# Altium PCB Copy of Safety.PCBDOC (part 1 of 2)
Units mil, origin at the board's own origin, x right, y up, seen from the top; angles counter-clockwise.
Board outline 11000 x 3900 mil, 4 copper layers (Top Layer, Grounds, +5V, Bottom Layer); 225 components, 170 nets, 779 pads, 129 vias.
Unrouted connection lines stored in the file: 11.
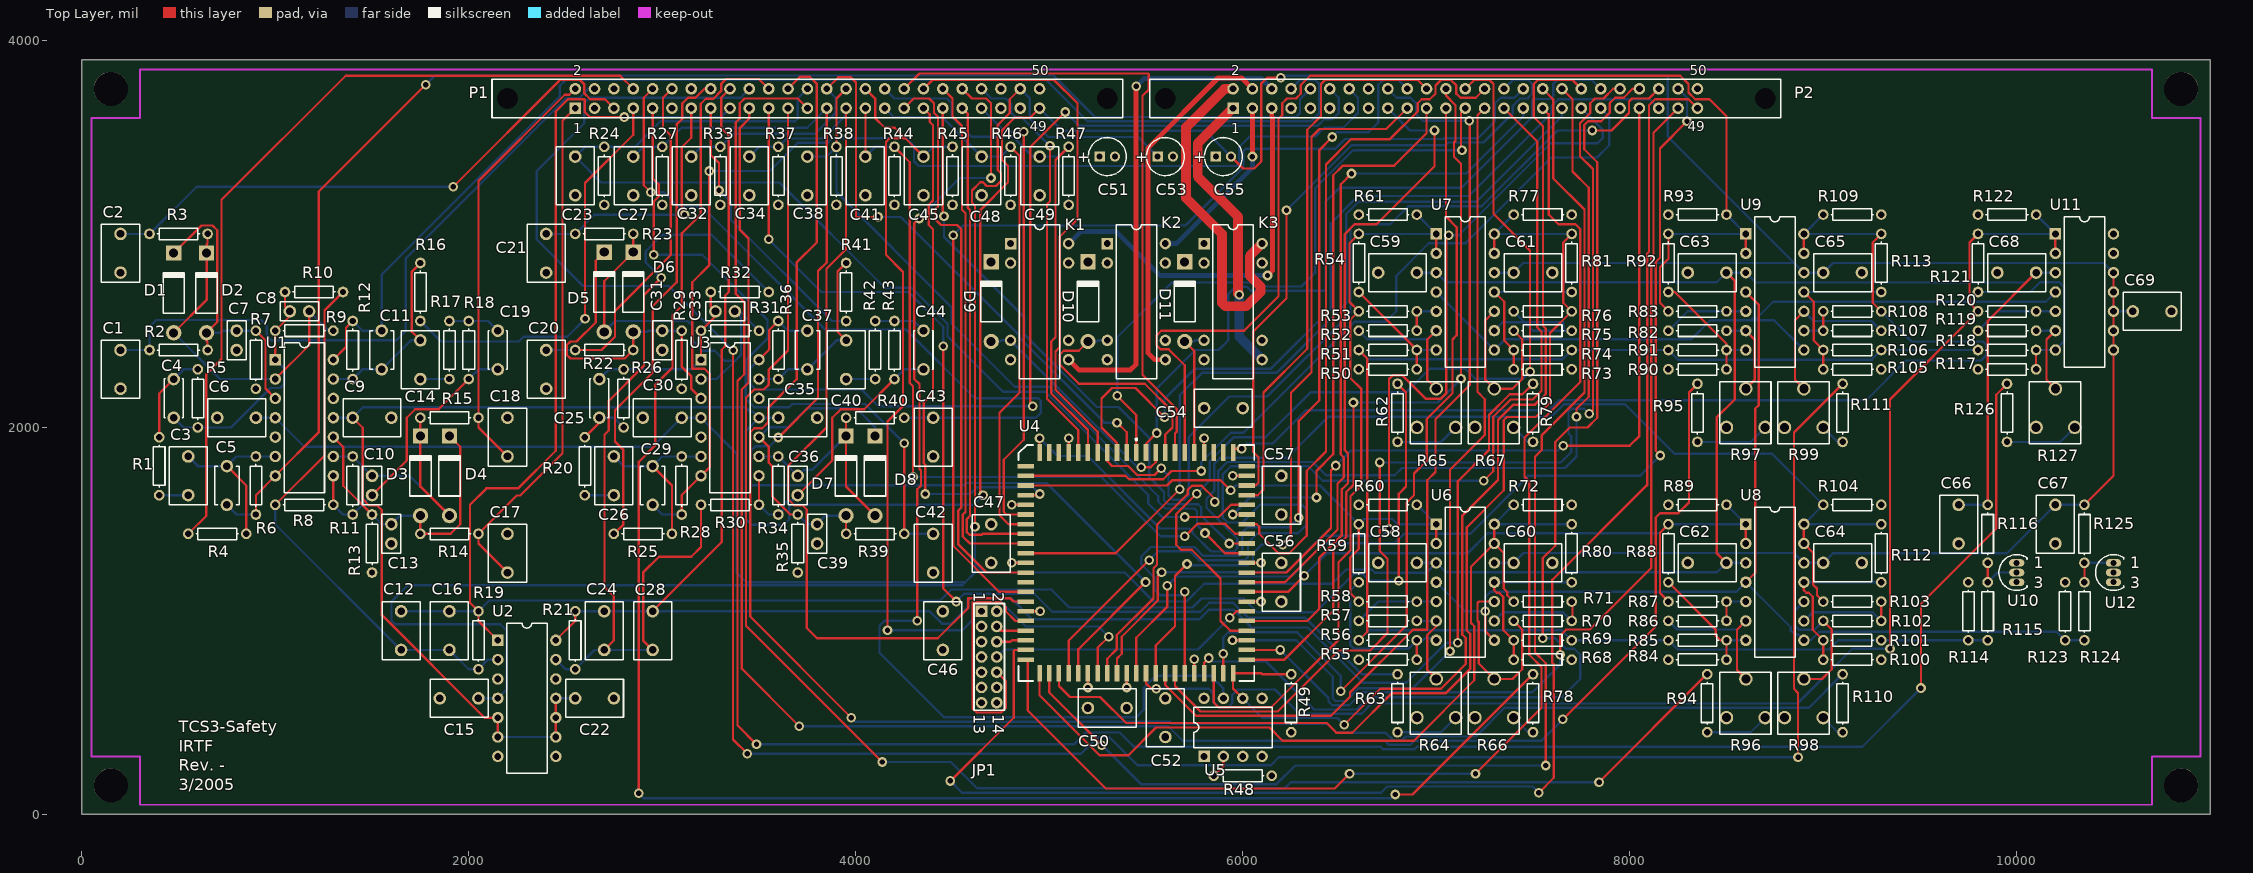
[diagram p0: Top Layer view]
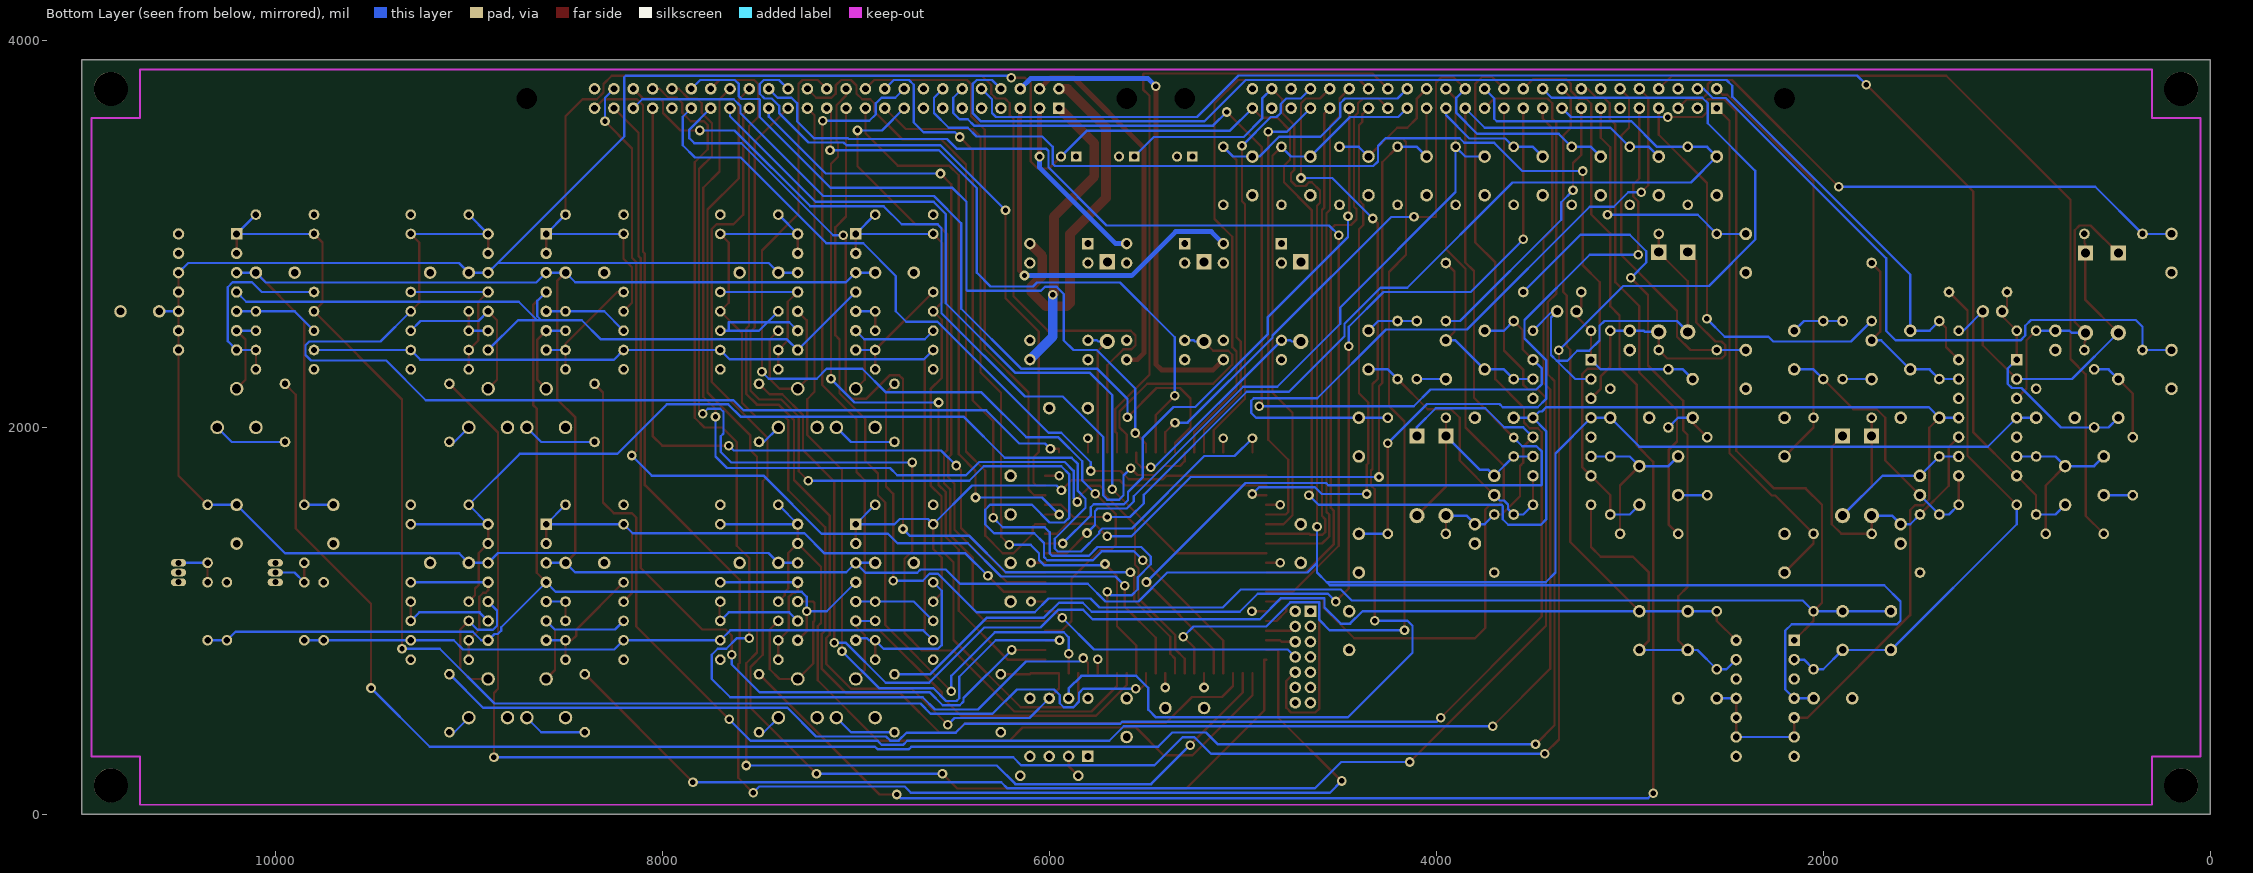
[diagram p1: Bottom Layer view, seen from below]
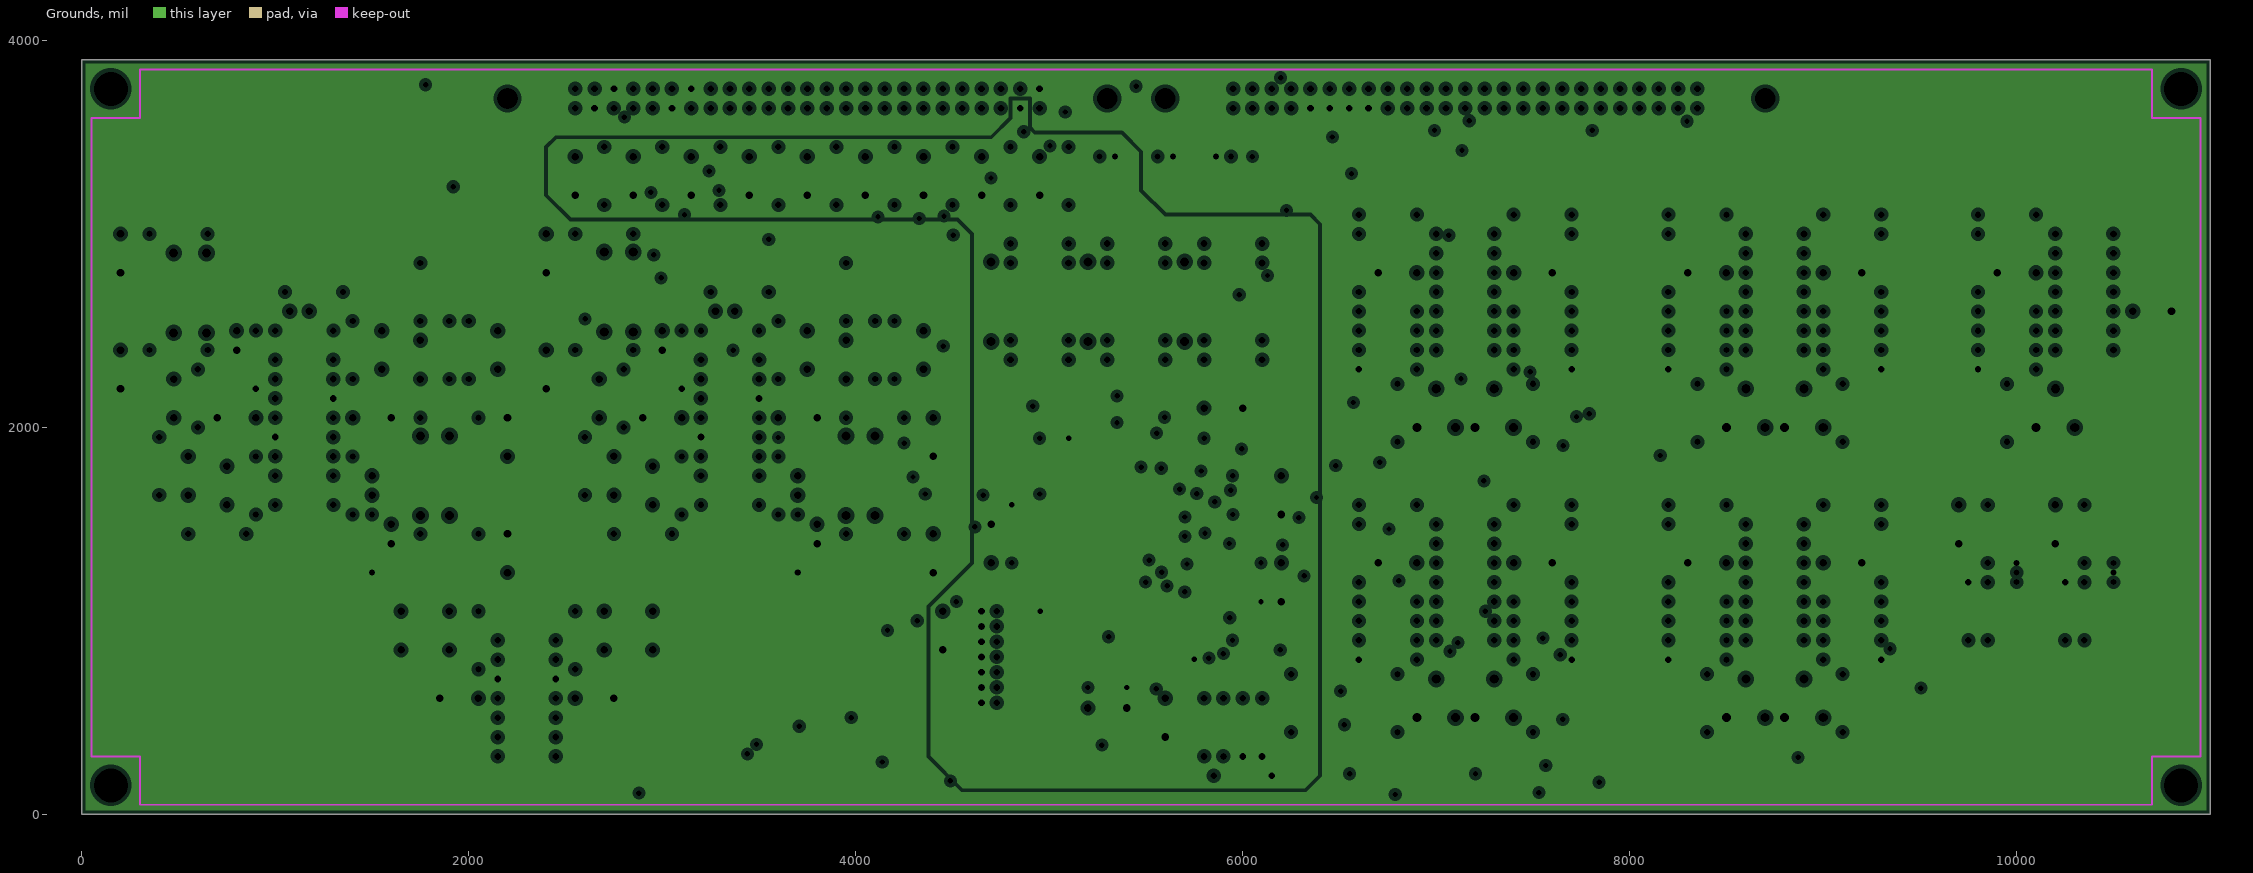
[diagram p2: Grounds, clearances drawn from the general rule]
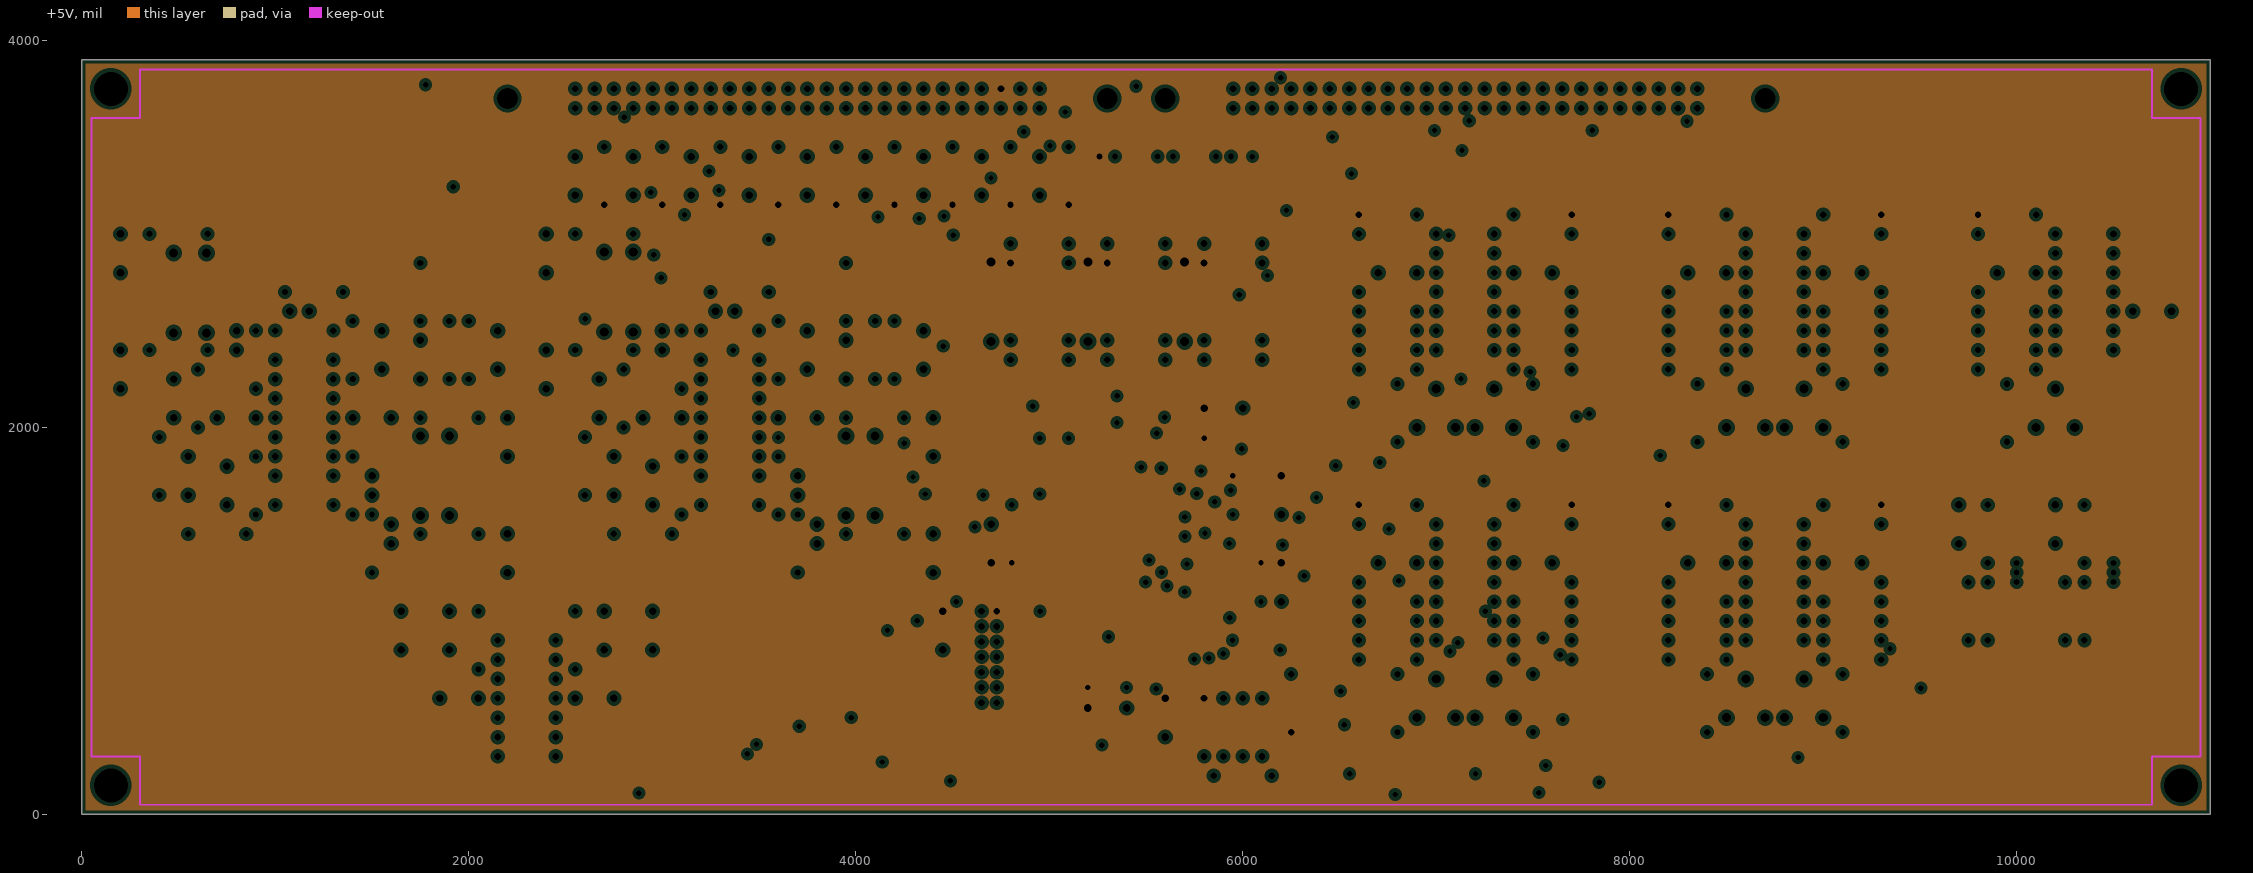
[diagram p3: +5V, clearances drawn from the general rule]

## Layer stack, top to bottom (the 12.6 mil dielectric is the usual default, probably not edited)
Top Layer: signal copper 1.4
Dielectric: core 12.6, FR-4, Dk 4.8
Grounds: plane copper 1.4, net (Multiple Nets)
Dielectric: prepreg 12.6, FR-4, Dk 4.8
+5V: plane copper 1.4, net VCC
Dielectric: core 12.6, FR-4, Dk 4.8
Bottom Layer: signal copper 1.4

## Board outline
0,0 11000,0 11000,3900 0,3900

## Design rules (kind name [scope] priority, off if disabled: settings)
Clearance [All] p1: gap=10
ComponentClearance [All] p1: gap=10 collisioncheckmode=0
HoleSize [All] p1: absolutevalues=TRUE maxlimit=200 minlimit=1 maxpercent=80.000 minpercent=20.000
PlaneClearance "Voltage Reg" [(InNet('NetR124_1') OR InNet('NetR115_1'))] p1: clearance=10
PlaneClearance [All] p2: clearance=20
PlaneConnect [All] p1: planeconnectstyle=Relief reliefexpansion=20 reliefentries=4 reliefconductorwidth=12 reliefairgap=12
PolygonConnect [All] p1: connectstyle=Relief reliefconductorwidth=10 reliefentries=4 polygonreliefangle="90 Angle"
RoomDefinition "U_Fault Comp" [InComponentClass('U_Fault Comp')] p1: confinementstyle=ConfineIn formatcopy=TRUE lockcomponents=FALSE outline 6553.27,753.27 6553.27,3146.73 10146.73,3146.73 10146.73,3101.73 10547.72,3101.73 10547.72,2712.36 10863.54,2712.36 10863.54,2487.64 10642.82,2487.64 10642.82,1143.66 10396.5,1143.66 10396.5,853.5 9346.73,853.5 9346.73,753.27 9146.73,753.27 9146.73,378.27 6753.27,378.27 6753.27,753.27
RoomDefinition "U_Fault Comp_1" [InComponentClass('U_Fault Comp')] p2: confinementstyle=ConfineIn formatcopy=TRUE lockcomponents=FALSE outline 6553.27,753.27 6553.27,3146.73 10146.73,3146.73 10146.73,3101.73 10547.72,3101.73 10547.72,2712.36 10863.54,2712.36 10863.54,2487.64 10642.82,2487.64 10642.82,1143.66 10396.5,1143.66 10396.5,853.5 9346.73,853.5 9346.73,753.27 9146.73,753.27 9146.73,378.27 6753.27,378.27 6753.27,753.27
RoomDefinition "U_Dec Tach" [InComponentClass('U_Dec Tach')] p3: confinementstyle=ConfineIn formatcopy=TRUE lockcomponents=FALSE outline 1786.46,487.64 1786.46,712.36 2287.64,712.36 2287.64,3063.54 2512.36,3063.54 2512.36,3046.73 2896.73,3046.73 2896.73,2959.53 2919.06,2959.53 2919.06,2896.73 3996.73,2896.73 3996.73,2596.73 4246.73,2596.73 4246.73,2549.69 4413.15,2549.69 4413.15,2113.54 4512.36,2113.54 4512.36,1186.46 3062.36,1186.46 3062.36,786.46 2813.54,786.46 2813.54,487.64
RoomDefinition "Safety Top" [InComponentClass('Safety Top')] p4: confinementstyle=ConfineIn formatcopy=TRUE lockcomponents=FALSE outline 2106.06,3502 2106.06,3887.98 8793.94,3887.98 8793.94,3502 6012.36,3502 6012.36,3287.64 5127.6,3287.64 5127.6,3502
RoomDefinition "U_Fault Logic" [InComponentClass('U_Fault Logic')] p5: confinementstyle=ConfineIn formatcopy=TRUE lockcomponents=FALSE outline 2237.64,3136.46 2237.64,3463.54 2478.27,3463.54 2478.27,3496.73 5371.73,3496.73 5371.73,3061.57 6147.72,3061.57 6147.72,1813.54 6312.36,1813.54 6312.36,1036.46 6296.73,1036.46 6296.73,378.27 6196.73,378.27 6196.73,153.27 5803.27,153.27 5803.27,252.28 5733.31,252.28 5733.31,277.02 4586.06,277.02 4586.06,786.46 4337.64,786.46 4337.64,3103.27 2478.27,3103.27 2478.27,3136.46
RoomDefinition "U_HA Tach" [InComponentClass('U_HA Tach')] p6: confinementstyle=ConfineIn formatcopy=TRUE lockcomponents=FALSE outline 87.64,2136.46 87.64,3063.54 312.36,3063.54 312.36,3046.73 696.73,3046.73 696.73,2954.53 714.06,2954.53 714.06,2896.73 1796.73,2896.73 1796.73,2596.73 2046.73,2596.73 2046.73,2549.69 2213.15,2549.69 2213.15,2113.54 2312.36,2113.54 2312.36,1001.73 2497.72,1001.73 2497.72,198.27 2102.28,198.27 2102.28,703.27 2003.27,703.27 2003.27,786.46 1537.64,786.46 1537.64,1203.27 1453.27,1203.27 1453.27,1403.27 503.27,1403.27 503.27,1586.46 437.64,1586.46 437.64,1603.27 353.27,1603.27 353.27,2136.46
RoutingVias [All] p1: holewidth=28 width=50 viastyle="Through Hole" minholewidth=28 minwidth=50 maxholewidth=28 maxwidth=50
SMDNeckDown [All] p1: percent=90.000
SolderMaskExpansion [All] p1: expansion=4
TestPointUsage [All] p1: valid=0 allowmultiple=FALSE
Testpoint [All] p1: side=15 testpointundercomponent=TRUE minsize=40 maxsize=100 preferedsize=60 minholesize=0 maxholesize=40 preferedholesize=32 testpointgrid=1 style=1023 order=-539222988
Width K3 [(InNet('NetK3_8') OR InNet('NetK3_14'))] p1: maxlimit=50 minlimit=50 preferedwidth=50
Width K1_K2 [(InNet('NetK2_8') OR InNet('NetK2_14') OR InNet('NetK1_8') OR InNet('NetK1_14'))] p2: maxlimit=25 minlimit=25 preferedwidth=25
Width [All] p3: maxlimit=12 minlimit=12 preferedwidth=12
14 further rules are at their usual default settings.

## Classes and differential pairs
component class "U_Fault Comp": C62 C64 C68 C69 R84 R85 R86 R87 R88 R89 R94 R96 R98 R100 R101 R102 R103 R104 R110 R112 R117 R118 R119 R120 R121 R122 R126 R127 U8 U11
component class "U_Fault Comp": C58 C59 C60 C61 C63 C65 C66 C67 R50 R51 R52 R53 R54 R55 R56 R57 R58 R59 R60 R61 R62 R63 R64 R65 R66 R67 R68 R69 R70 R71 R72 R73 R74 R75 R76 R77 R78 R79 R80 R81 R82 R83 R90 R91 R92 R93 R95 R97 R99 R105 R106 R107 R108 R109 R111 R113 R114 R115 R116 R123 R124 R125 U6 U7 U9 U10 U12
component class "Safety Top": C51 C53 C55 P1 P2
component class "U_Dec Tach": C15 C20 C21 C22 C24 C25 C26 C28 C29 C30 C31 C33 C35 C36 C37 C39 C40 C42 C43 C44 D5 D6 D7 D8 R20 R21 R22 R23 R25 R26 R28 R29 R30 R31 R32 R34 R35 R36 R39 R40 R41 R42 R43 U3
component class "U_Fault Logic": C23 C27 C32 C34 C38 C41 C45 C46 C47 C48 C49 C50 C52 C54 C56 C57 D9 D10 D11 JP1 K1 K2 K3 R24 R27 R33 R37 R38 R44 R45 R46 R47 R48 R49 U4 U5
component class "U_HA Tach": C1 C2 C3 C4 C5 C6 C7 C8 C9 C10 C11 C12 C13 C14 C16 C17 C18 C19 D1 D2 D3 D4 R1 R2 R3 R4 R5 R6 R7 R8 R9 R10 R11 R12 R13 R14 R15 R16 R17 R18 R19 U1 U2

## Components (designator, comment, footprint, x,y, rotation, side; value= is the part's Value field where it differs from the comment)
C1 "0.1uF" capr5.08-7.6x5 200,2300 r270 top
C2 "0.1uF" capr5.08-7.6x5 200,2900 r270 top
C3 "0.33uF" capr5.08-7.6x5 550,1750 r90 top
C4 "0.068uF" capr5.08-5.1x2.5 475,2150 r90 top
C5 "2200pF" capr5.08-5.1x3.2 750,1700 r270 top
C6 "0.1uF" capr5.08-7.6x5 800,2050 r180 top
C7 "0.022uF" capr2.54-5.1x2.5 800,2450 r270 top
C8 "0.022uF" capr2.54-5.1x2.5 1125,2600 r180 top
C9 "0.1uF" capr5.08-7.6x5 1500,2050 r0 top
C10 "0.022uF" capr2.54-5.1x2.5 1500,1700 r270 top
C11 "2200pF" capr5.08-5.1x3.2 1550,2400 r90 top
C12 "1uF" capr5.08-7.6x5 1650,950 r90 top
C13 "0.022uF" capr2.54-5.1x2.5 1600,1450 r270 top
C14 "0.33uF" capr5.08-7.6x5 1750,2350 r90 top
C15 "0.1uF" capr5.08-7.6x5 1950,600 r180 top
C16 "0.22uF" capr5.08-7.6x5 1900,950 r90 top
C17 "0.1uF" capr5.08-7.6x5 2200,1350 r90 top
C18 "0.1uF" capr5.08-7.6x5 2200,1950 r90 top
C19 "0.068uF" capr5.08-5.1x2.5 2150,2400 r90 top
C20 "0.1uF" capr5.08-7.6x5 2400,2300 r270 top
C21 "0.1uF" capr5.08-7.6x5 2400,2900 r270 top
C22 "0.1uF" capr5.08-7.6x5 2650,600 r0 top
C23 "0.22uF" capr5.08-7.6x5 2550,3300 r270 top
C24 "0.22uF" capr5.08-7.6x5 2700,950 r90 top
C25 "0.068uF" capr5.08-5.1x2.5 2675,2150 r270 top
C26 "0.33uF" capr5.08-7.6x5 2750,1750 r90 top
C27 "0.22uF" capr5.08-7.6x5 2850,3300 r270 top
C28 "1uF" capr5.08-7.6x5 2950,950 r90 top
C29 "Cap" capr5.08-5.1x3.2 2950,1700 r270 top
C30 "0.1uF" capr5.08-7.6x5 3000,2050 r180 top
C31 "0.022uF" capr2.54-5.1x2.5 3000,2450 r270 top
C32 "0.22uF" capr5.08-7.6x5 3150,3300 r270 top
C33 "0.022uF" capr2.54-5.1x2.5 3325,2600 r180 top
C34 "0.22uF" capr5.08-7.6x5 3450,3300 r270 top
C35 "0.1uF" capr5.08-7.6x5 3700,2050 r0 top
C36 "0.022uF" capr2.54-5.1x2.5 3700,1700 r270 top
C37 "Cap" capr5.08-5.1x3.2 3750,2400 r90 top
C38 "0.22uF" capr5.08-7.6x5 3750,3300 r270 top
C39 "0.022uF" capr2.54-5.1x2.5 3800,1450 r270 top
C40 "0.33uF" capr5.08-7.6x5 3950,2350 r90 top
C41 "0.22uF" capr5.08-7.6x5 4050,3300 r270 top
C42 "0.1uF" capr5.08-7.6x5 4400,1350 r270 top
C43 "0.1uF" capr5.08-7.6x5 4400,1950 r270 top
C44 "0.068uF" capr5.08-5.1x2.5 4350,2400 r90 top
C45 "0.22uF" capr5.08-7.6x5 4350,3300 r270 top
C46 "0.1uF" capr5.08-7.6x5 4450,950 r270 top
C47 "0.1uF" capr5.08-7.6x5 4700,1400 r90 top
C48 "0.22uF" capr5.08-7.6x5 4650,3300 r270 top
C49 "0.22uF" capr5.08-7.6x5 4950,3300 r270 top
C50 "0.1uF" capr5.08-7.6x5 5300,550 r0 top
C51 "33uF" cappr2-5x11 5300,3400 r0 top
C52 "0.1uF" capr5.08-7.6x5 5600,500 r270 top
C53 "22uF" cappr2-5x11 5600,3400 r0 top
C54 "0.1uF" capr5.08-7.6x5 5900,2100 r0 top
C55 "22uF" cappr2-5x11 5900,3400 r0 top
C56 "0.1uF" capr5.08-7.6x5 6200,1200 r270 top
C57 "0.1uF" capr5.08-7.6x5 6200,1650 r270 top
C58 "0.1uF" capr5.08-7.6x5 6800,1300 r180 top
C59 "0.1uF" capr5.08-7.6x5 6800,2800 r180 top
C60 "0.1uF" capr5.08-7.6x5 7500,1300 r0 top
C61 "0.1uF" capr5.08-7.6x5 7500,2800 r0 top
C62 "0.1uF" capr5.08-7.6x5 8400,1300 r180 top
C63 "0.1uF" capr5.08-7.6x5 8400,2800 r180 top
C64 "0.1uF" capr5.08-7.6x5 9100,1300 r0 top
C65 "0.1uF" capr5.08-7.6x5 9100,2800 r0 top
C66 "0.1uF" capr5.08-7.6x5 9700,1500 r270 top
C67 "0.1uF" capr5.08-7.6x5 10200,1500 r270 top
C68 "0.1uF" capr5.08-7.6x5 10000,2800 r180 top
C69 "0.1uF" capr5.08-7.6x5 10700,2600 r0 top
D1 "1N4005" DIO10.46-5.3x2.8 475,2695 r90 top
D2 "1N4005" DIO10.46-5.3x2.8 645,2695 r90 top
D3 "1N4005" DIO10.46-5.3x2.8 1750,1750 r90 top
D4 "1N4005" DIO10.46-5.3x2.8 1900,1750 r90 top
D5 "1N4005" DIO10.46-5.3x2.8 2700,2700 r90 top
D6 "1N4005" DIO10.46-5.3x2.8 2850,2700 r90 top
D7 "1N4005" DIO10.46-5.3x2.8 3950,1750 r90 top
D8 "1N4005" DIO10.46-5.3x2.8 4100,1750 r90 top
D9 "1N5817" DIO10.46-5.3x2.8 4700,2650 r90 top
D10 "1N5817" DIO10.46-5.3x2.8 5200,2650 r90 top
D11 "1N5817" DIO10.46-5.3x2.8 5700,2650 r90 top
JP1 "Header 7X2" HDR2X7-2mm 4650,1050 r270 top
K1 "RELAY-SPST" "Reed Dip-14" 4800,2950 r270 top
K2 "RELAY-SPST" "Reed Dip-14" 5300,2950 r270 top
K3 "RELAY-SPST" "Reed Dip-14" 5800,2950 r270 top
P1 "HEADER 50" HDR2X25-Latch 2550,3650 r0 top
P2 "HEADER 50" HDR2X25-Latch 5950,3650 r0 top
R1 "56.2k" AXIAL-0.3 400,1800 r270 top
R2 "47.5k" AXIAL-0.3 500,2400 r180 top
R3 "47.5k" AXIAL-0.3 500,3000 r180 top
R4 "100k" AXIAL-0.3 700,1450 r0 top
R5 "68.1k" AXIAL-0.3 600,2150 r90 top
R6 "301k" AXIAL-0.3 900,1700 r270 top
R7 "10k" AXIAL-0.3 900,2350 r270 top
R8 "68.1k" AXIAL-0.3 1150,1600 r180 top
R9 "10k" AXIAL-0.3 1150,2500 r180 top
R10 "68.1k" AXIAL-0.3 1200,2700 r180 top
R11 "10k" AXIAL-0.3 1400,1700 r270 top
R12 "301k" AXIAL-0.3 1400,2400 r90 top
R13 "10k" AXIAL-0.3 1500,1400 r270 top
R14 "47.5k" AXIAL-0.3 1900,1450 r0 top
R15 "47.5k" AXIAL-0.3 1900,2050 r0 top
R16 "100k" AXIAL-0.3 1750,2700 r90 top
R17 "56.2k" AXIAL-0.3 1900,2400 r270 top
R18 "68.1k" AXIAL-0.3 2000,2400 r90 top
R19 "33.2k" AXIAL-0.3 2050,900 r270 top
R20 "56.2k" AXIAL-0.3 2600,1800 r270 top
R21 "33.2k" AXIAL-0.3 2550,900 r270 top
R22 "47.5k" AXIAL-0.3 2700,2400 r180 top
R23 "47.5k" AXIAL-0.3 2700,3000 r180 top
R24 "1k" AXIAL-0.3 2700,3300 r270 top
R25 "100k" AXIAL-0.3 2900,1450 r0 top
R26 "68.1k" AXIAL-0.3 2800,2150 r270 top
R27 "1k" AXIAL-0.3 3000,3300 r270 top
R28 "301k" AXIAL-0.3 3100,1700 r270 top
R29 "10k" AXIAL-0.3 3100,2350 r270 top
R30 "68.1k" AXIAL-0.3 3350,1600 r180 top
R31 "10k" AXIAL-0.3 3350,2500 r180 top
R32 "68.1k" AXIAL-0.3 3400,2700 r180 top
R33 "1k" AXIAL-0.3 3300,3300 r270 top
R34 "10k" AXIAL-0.3 3600,1700 r270 top
R35 "10k" AXIAL-0.3 3700,1400 r270 top
R36 "301k" AXIAL-0.3 3600,2400 r90 top
R37 "1k" AXIAL-0.3 3600,3300 r270 top
R38 "1k" AXIAL-0.3 3900,3300 r270 top
R39 "47.5k" AXIAL-0.3 4100,1450 r0 top
R40 "47.5k" AXIAL-0.3 4100,2050 r0 top
R41 "100k" AXIAL-0.3 3950,2700 r90 top
R42 "56.2k" AXIAL-0.3 4100,2400 r270 top
R43 "68.1k" AXIAL-0.3 4200,2400 r90 top
R44 "1k" AXIAL-0.3 4200,3300 r270 top
R45 "1k" AXIAL-0.3 4500,3300 r270 top
R46 "1k" AXIAL-0.3 4800,3300 r270 top
R47 "1k" AXIAL-0.3 5100,3300 r270 top
R48 "0" AXIAL-0.3 6000,200 r0 top
R49 "10k" AXIAL-0.3 6250,575 r270 top
R50 "1M" AXIAL-0.3 6750,2300 r180 top
R51 "1M" AXIAL-0.3 6750,2400 r0 top
R52 "10k" AXIAL-0.3 6750,2500 r0 top
R53 "10M" AXIAL-0.3 6750,2600 r180 top
R54 "1M" AXIAL-0.3 6600,2850 r90 top
R55 "1M" AXIAL-0.3 6750,800 r180 top
R56 "1M" AXIAL-0.3 6750,900 r0 top
R57 "10k" AXIAL-0.3 6750,1000 r180 top
R58 "10M" AXIAL-0.3 6750,1100 r180 top
R59 "1M" AXIAL-0.3 6600,1350 r90 top
R60 "3.09k" AXIAL-0.3 6750,1600 r0 top
R61 "3.09k" AXIAL-0.3 6750,3100 r0 top
R62 "10k" AXIAL-0.3 6800,2075 r270 top
R63 "10k" AXIAL-0.3 6800,575 r270 top
R64 "50k" "307 Pot" 6900,500 r0 top
R65 "50k" "307 Pot" 6900,2000 r0 top
R66 "50k" "307 Pot" 7200,500 r0 top
R67 "50k" "307 Pot" 7200,2000 r0 top
R68 "1M" AXIAL-0.3 7550,800 r0 top
R69 "1M" AXIAL-0.3 7550,900 r180 top
R70 "10k" AXIAL-0.3 7550,1000 r0 top
R71 "10M" AXIAL-0.3 7550,1100 r180 top
R72 "3.09k" AXIAL-0.3 7550,1600 r180 top
R73 "1M" AXIAL-0.3 7550,2300 r0 top
R74 "1M" AXIAL-0.3 7550,2400 r180 top
R75 "10k" AXIAL-0.3 7550,2500 r0 top
R76 "10M" AXIAL-0.3 7550,2600 r0 top
R77 "3.09k" AXIAL-0.3 7550,3100 r180 top
R78 "10k" AXIAL-0.3 7500,575 r270 top
R79 "10k" AXIAL-0.3 7500,2075 r270 top
R80 "1M" AXIAL-0.3 7700,1350 r90 top
R81 "1M" AXIAL-0.3 7700,2850 r90 top
R82 "10k" AXIAL-0.3 8350,2500 r180 top
R83 "10M" AXIAL-0.3 8350,2600 r180 top
R84 "1M" AXIAL-0.3 8350,800 r180 top
R85 "1M" AXIAL-0.3 8350,900 r0 top
R86 "10k" AXIAL-0.3 8350,1000 r0 top
R87 "10M" AXIAL-0.3 8350,1100 r180 top
R88 "1M" AXIAL-0.3 8200,1350 r90 top
R89 "3.09k" AXIAL-0.3 8350,1600 r0 top
R90 "1M" AXIAL-0.3 8350,2300 r180 top
R91 "1M" AXIAL-0.3 8350,2400 r0 top
R92 "1M" AXIAL-0.3 8200,2850 r90 top
R93 "3.09k" AXIAL-0.3 8350,3100 r0 top
R94 "10k" AXIAL-0.3 8400,575 r270 top
R95 "10k" AXIAL-0.3 8350,2075 r270 top
R96 "50k" "307 Pot" 8500,500 r0 top
R97 "50k" "307 Pot" 8500,2000 r0 top
R98 "50k" "307 Pot" 8800,500 r0 top
R99 "50k" "307 Pot" 8800,2000 r0 top
R100 "1M" AXIAL-0.3 9150,800 r0 top
R101 "1M" AXIAL-0.3 9150,900 r180 top
R102 "10k" AXIAL-0.3 9150,1000 r0 top
R103 "10M" AXIAL-0.3 9150,1100 r180 top
R104 "3.09k" AXIAL-0.3 9150,1600 r180 top
R105 "1M" AXIAL-0.3 9150,2300 r0 top
R106 "1M" AXIAL-0.3 9150,2400 r180 top
R107 "10k" AXIAL-0.3 9150,2500 r180 top
R108 "10M" AXIAL-0.3 9150,2600 r0 top
R109 "3.09k" AXIAL-0.3 9150,3100 r180 top
R110 "10k" AXIAL-0.3 9100,575 r270 top
R111 "10k" AXIAL-0.3 9100,2075 r270 top
R112 "1M" AXIAL-0.3 9300,1350 r90 top
R113 "1M" AXIAL-0.3 9300,2850 r90 top
R114 "20k" AXIAL-0.3 9750,1050 r90 top
R115 "30.1k" AXIAL-0.3 9850,1050 r270 top
R116 "7.50k" AXIAL-0.3 9850,1450 r90 top
R117 "1M" AXIAL-0.3 9950,2300 r180 top
R118 "1M" AXIAL-0.3 9950,2400 r0 top
R119 "10k" AXIAL-0.3 9950,2500 r180 top
R120 "10M" AXIAL-0.3 9950,2600 r180 top
R121 "1M" AXIAL-0.3 9800,2850 r90 top
R122 "3.09k" AXIAL-0.3 9950,3100 r0 top
R123 "20k" AXIAL-0.3 10250,1050 r90 top
R124 "30.1k" AXIAL-0.3 10350,1050 r270 top
R125 "7.50k" AXIAL-0.3 10350,1450 r90 top
R126 "10k" AXIAL-0.3 9950,2075 r270 top
R127 "50k" "307 Pot" 10100,2000 r0 top
U1 "MAX479CPD" PD14 1150,2050 r270 top
U2 "MAX479CPD" PD14 2300,600 r270 top
U3 "MAX479CPD" PD14 3350,2050 r270 top
U4 "XC9572-15PC84C" PC84 5450,1300 r0 top
U5 "MAX1232EPA" PA8 5950,450 r0 top
U6 "LM339AN" N14A 7150,1200 r270 top
U7 "LM339AN" N14A 7150,2700 r270 top
U8 "LM339AN" N14A 8750,1200 r270 top
U9 "LM339AN" N14A 8750,2700 r270 top
U10 "LM336BZ2.5" Z03A 10000,1250 r0 top
U11 "LM339AN" N14A 10350,2700 r270 top
U12 "LM336BZ2.5" Z03A 10500,1250 r0 top

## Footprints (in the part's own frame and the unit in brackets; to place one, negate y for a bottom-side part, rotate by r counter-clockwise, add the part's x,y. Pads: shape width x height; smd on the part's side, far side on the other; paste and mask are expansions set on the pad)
"307 Pot" [mil]
  round 70 hole 46.9: 1(0,0) 2(200,0) 3(100,200)
  silkscreen extent -35,-85 230,235
AXIAL-0.3 [mm] "Resistor; 2 Leads"
  round 1.4 hole 0.838: 1(-3.81,0) 2(3.81,0)
  silkscreen extent -2.77,-0.76 2.77,0.76
cappr2-5x11 [mm]
  rect 1.35x1.35 hole 0.787: 1(-1,0)
  round 1.35 hole 0.787: 2(1,0)
  silkscreen extent -2.5,-2.5 2.5,2.5
capr2.54-5.1x2.5 [mm]
  round 1.65 hole 0.991: 1(-1.27,0) 2(1.27,0)
  silkscreen extent -2.55,-1.25 2.55,1.25
capr5.08-5.1x2.5 [mm]
  round 1.65 hole 0.991: 1(-2.54,0) 2(2.54,0)
  silkscreen extent -2.55,-1.25 2.55,1.25
capr5.08-5.1x3.2 [mm]
  round 1.65 hole 0.991: 1(-2.54,0) 2(2.54,0)
  silkscreen extent -2.55,-1.6 2.55,1.6
capr5.08-7.6x5 [mm]
  round 1.65 hole 0.991: 1(-2.54,0) 2(2.54,0)
  silkscreen extent -3.8,-2.5 3.8,2.5
DIO10.46-5.3x2.8 [mm] "Diode, Axial; Body 5.2 x 2.7 mm (LxDia. max), Lead Dia. 0.86 mm (max)"
  round 2 hole 1.191: 1(-5.23,0)
  rect 2x2 hole 1.191: 2(5.23,0)
  silkscreen extent -2.65,-1.41 2.75,1.4
HDR2X7-2mm [mil]
  rect 60x60 hole 35: 1(0,0)
  round 60 hole 35: 2(0,78.74) 3(78.74,0) 4(78.74,78.74) 5(157.48,0) 6(157.48,78.74) 7(236.22,0) 8(236.22,78.74) 9(314.96,0) 10(314.96,78.74) 11(393.7,0) 12(393.7,78.74) 13(472.44,0) 14(472.44,78.74)
  silkscreen extent -39,-39 512,118
HDR2X25-Latch [mil]
  round 0 hole 106.5 unplated: 0(-350,50) 0(2750,50)
  rect 60x60 hole 35: 1(0,0)
  round 60 hole 35: 2(0,100) 3(100,0) 4(100,100) 5(200,0) 6(200,100) 7(300,0) 8(300,100) 9(400,0) 10(400,100) 11(500,0) 12(500,100) 13(600,0) 14(600,100) 15(700,0) 16(700,100) 17(800,0) 18(800,100) 19(900,0) 20(900,100) 21(1000,0) 22(1000,100) 23(1100,0) 24(1100,100) 25(1200,0) 26(1200,100) 27(1300,0) 28(1300,100) 29(1400,0) 30(1400,100) 31(1500,0) 32(1500,100) 33(1600,0) 34(1600,100) 35(1700,0) 36(1700,100) 37(1800,0) 38(1800,100) 39(1900,0) 40(1900,100) 41(2000,0) 42(2000,100) 43(2100,0) 44(2100,100) 45(2200,0) 46(2200,100) 47(2300,0) 48(2300,100) 49(2400,0) 50(2400,100)
  silkscreen extent -430,-50 2830,150
N14A [mm] "DIP; 14 Leads; Row Spacing 7.62 mm; Pitch 2.54 mm"
  rect 1.5x1.5 hole 0.889: 1(-7.62,-3.81)
  round 1.5 hole 0.889: 2(-5.08,-3.81) 3(-2.54,-3.81) 4(0,-3.81) 5(2.54,-3.81) 6(5.08,-3.81) 7(7.62,-3.81) 8(7.62,3.81) 9(5.08,3.81) 10(2.54,3.81) 11(0,3.81) 12(-2.54,3.81) 13(-5.08,3.81) 14(-7.62,3.81)
  silkscreen extent -9.85,-2.65 9.85,2.65
PA8 [mm] "DIP; 8 Leads; Row Spacing 7.62 mm; Pitch 2.54 mm"
  rect 1.5x1.5 hole 0.889: 1(-3.81,-3.81)
  round 1.5 hole 0.889: 2(-1.27,-3.81) 3(1.27,-3.81) 4(3.81,-3.81) 5(3.81,3.81) 6(1.27,3.81) 7(-1.27,3.81) 8(-3.81,3.81)
  silkscreen extent -5.15,-2.65 5.15,2.65
PC84 [mm] "84-Pin Plastic Leaded Chip Carrier (PC84)"
  rect 0.6x2.2 smd: 1(0,14.5) 2(-1.27,14.5) 3(-2.54,14.5) 4(-3.81,14.5) 5(-5.08,14.5) 6(-6.35,14.5) 7(-7.62,14.5) 8(-8.89,14.5) 9(-10.16,14.5) 10(-11.43,14.5) 11(-12.7,14.5) 33(-12.7,-14.5) 34(-11.43,-14.5) 35(-10.16,-14.5) 36(-8.89,-14.5) 37(-7.62,-14.5) 38(-6.35,-14.5) 39(-5.08,-14.5) 40(-3.81,-14.5) 41(-2.54,-14.5) 42(-1.27,-14.5) 43(0,-14.5) 44(1.27,-14.5) 45(2.54,-14.5) 46(3.81,-14.5) 47(5.08,-14.5) 48(6.35,-14.5) 49(7.62,-14.5) 50(8.89,-14.5) 51(10.16,-14.5) 52(11.43,-14.5) 53(12.7,-14.5) 75(12.7,14.5) 76(11.43,14.5) 77(10.16,14.5) 78(8.89,14.5) 79(7.62,14.5) 80(6.35,14.5) 81(5.08,14.5) 82(3.81,14.5) 83(2.54,14.5) 84(1.27,14.5)
  rect 2.2x0.6 smd: 12(-14.5,12.7) 13(-14.5,11.43) 14(-14.5,10.16) 15(-14.5,8.89) 16(-14.5,7.62) 17(-14.5,6.35) 18(-14.5,5.08) 19(-14.5,3.81) 20(-14.5,2.54) 21(-14.5,1.27) 22(-14.5,0) 23(-14.5,-1.27) 24(-14.5,-2.54) 25(-14.5,-3.81) 26(-14.5,-5.08) 27(-14.5,-6.35) 28(-14.5,-7.62) 29(-14.5,-8.89) 30(-14.5,-10.16) 31(-14.5,-11.43) 32(-14.5,-12.7) 54(14.5,-12.7) 55(14.5,-11.43) 56(14.5,-10.16) 57(14.5,-8.89) 58(14.5,-7.62) 59(14.5,-6.35) 60(14.5,-5.08) 61(14.5,-3.81) 62(14.5,-2.54) 63(14.5,-1.27) 64(14.5,0) 65(14.5,1.27) 66(14.5,2.54) 67(14.5,3.81) 68(14.5,5.08) 69(14.5,6.35) 70(14.5,7.62) 71(14.5,8.89) 72(14.5,10.16) 73(14.5,11.43) 74(14.5,12.7)
  silkscreen extent -15.48,-15.49 15.48,16.32
PD14 [mm] "DIP; 14 Leads; Row Spacing 7.62 mm; Pitch 2.54 mm"
  rect 1.5x1.5 hole 0.889: 1(-7.62,-3.81)
  round 1.5 hole 0.889: 2(-5.08,-3.81) 3(-2.54,-3.81) 4(0,-3.81) 5(2.54,-3.81) 6(5.08,-3.81) 7(7.62,-3.81) 8(7.62,3.81) 9(5.08,3.81) 10(2.54,3.81) 11(0,3.81) 12(-2.54,3.81) 13(-5.08,3.81) 14(-7.62,3.81)
  silkscreen extent -9.85,-2.65 9.85,2.65
"Reed Dip-14" [mm]
  rect 1.5x1.5 hole 0.889: 1(0,0)
  round 1.5 hole 0.889: 2(2.54,0) 6(12.7,0) 7(15.24,0) 8(15.24,7.62) 9(12.7,7.62) 13(2.54,7.62) 14(0,7.62)
  silkscreen extent -2.48,1.16 17.72,6.46
Z03A [mm] "TO, Flat Index; 3 In-Line, Axial Leads; Body Dia. 4.6mm; Leads 0.53 x 0.39 mm (max)"
  oval 2x1 hole 0.787: 1(0,1.27) 2(0,0) 3(0,-1.27)
  silkscreen extent -2.34,-2.34 1.35,2.34

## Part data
C1 C2 C6 C9 C15 C17 C18 C20 C21 C22 C30 C35 C42 C43 C46 C47 C50 C52 C54 C56 C57 C58 C59 C60 C61 C62 C63 C64 C65 C66 C67 C68 C69: library part Cap, "CAP .1UF 50V STACK METAL FILM"
C3 C14 C26 C40: library part Cap, "CAP .33UF 50V STACK METAL FILM"
C4 C19 C25 C44: library part Cap, "CAP .068UF 50V CERAMIC MONO 10%"
C5 C11: library part Cap, "CAP 2200PF 50V CERAMIC MONO 5%"
C7 C8 C10 C13 C31 C33 C36 C39: library part Cap, "0.022uF Capacitor"
C12 C28: library part Cap, "CAP 1UF 50V STACK METAL FILM"
C16 C23 C24 C27 C32 C34 C38 C41 C45 C48 C49: library part Cap, "CAP .22UF 50V CERAMIC MONO 10%"
C29 C37: "CAP 2200PF 50V CERAMIC MONO 5%"
C51: library part "Cap Pol2", "CAP 33UF 16V ALUM LYTIC RADIAL"
C53 C55: library part "Cap Pol2", "CAP 22UF 25V ALUM LYTIC RADIAL"
D1 D2 D3 D4 D5 D6 D7 D8: library part "Diode 1N4005", "RECTIFIER 1 AMP 600V DO-41"
D9 D10 D11: library part "Diode 11DQ03", "RECTIFIER SCHOTTKY 1A 20V DO-41"
JP1: "CONN HEADER 14POS 2MM VERT GOLD"
K1 K2 K3: library part "Reed Relay", "RELAY REED SPST 5VDC DIP"
P1 P2: library part "Header 50", "4 pin Header"
R1 R17 R20 R42: library part Res1, "RES 56.2K OHM 1/4W 1% METAL FILM"
R2 R3 R14 R15 R22 R23 R39 R40: library part Res1, "RES 47.5K OHM 1/4W 1% METAL FILM"
R4 R16 R25 R41: library part Res1, "RES 100K OHM 1/4W 1% METAL FILM"
R5 R8 R10 R18 R26 R30 R32 R43: library part Res1, "68.1k ohm resistor"
R6 R12 R28 R36: library part Res1, "RES 301K OHM 1/4W 1% METAL FILM"
R7 R9 R11 R13 R29 R31 R34 R35 R49 R52 R57 R62 R63 R70 R75 R78 R79 R82 R86 R94 R95 R102 R107 R110 R111 R119 R126: library part Res1, "10k ohm resistor"
R19 R21: library part Res1, "RES 33.2K OHM 1/4W 1% METAL FILM"
R24 R27 R33 R37 R38 R44 R45 R46 R47: library part Res1, "RES 1.00K OHM 1/4W 1% METAL FILM"
R48: library part Res1, "JUMPER ZERO OHM 1/4W"
R50 R51 R54 R55 R56 R59 R68 R69 R73 R74 R80 R81 R84 R85 R88 R90 R91 R92 R100 R101 R105 R106 R112 R113 R117 R118 R121: library part Res1, "1.0M ohm resistor"
R53 R58 R71 R76 R83 R87 R103 R108 R120: library part Res1, "RES 10 MEG 1/4 W 5% CARBON FILM"
R60 R61 R72 R77 R89 R93 R104 R109 R122: library part Res1, "RES 3.09K OHM 1/4W 1% METAL FILM"
R64 R65 R66 R67 R96 R97 R98 R99 R127: library part RPot, "POT 50K OHM 6MM CERMET HORZ"
R114 R123: library part Res1, "20k ohm resistor"
R115 R124: library part Res1, "RES 30.1K OHM 1/4W 1% METAL FILM"
R116 R125: library part Res1, "RES 7.50K OHM 1/4W 1% METAL FILM"
U1 U2 U3: "IC OPAMP SNGL SUP QUAD 14-DIP"
U4: "IC CPLD 72 MACROCELL 84-PLCC"
U5: "IC MPU SUPERVISORY CIRCUIT 8-DIP"
U6 U7 U8 U9 U11: "IC COMPRTR QUAD 0-70DEG C 14-DIP"
U10 U12: "IC REFERENCE DIODE 2.5V TO-92"

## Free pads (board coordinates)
  round 175 hole 175 unplated: 0(150,150) 1(10850,150) 2(10850,3750) 3(150,3750)

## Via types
v1: diameter 50, hole 28, Top Layer to Bottom Layer, 129 vias

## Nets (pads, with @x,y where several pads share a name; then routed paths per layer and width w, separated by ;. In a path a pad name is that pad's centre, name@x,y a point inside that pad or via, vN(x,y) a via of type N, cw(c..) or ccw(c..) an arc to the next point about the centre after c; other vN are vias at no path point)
1V: R51.1 R56.1 R69.1 R74.1 R85.1 R91.1 R101.1 R106.1 R114.1 R115.2 R118.1 | length 8150.5
  Top Layer w12: R56.1@6600,900 6644,944 6644,2356 R51.1@6600,2400
  Bottom Layer w12: R56.1@6600,900 6652.04,952.04 7647.96,952.04 R69.1@7700,900 R85.1@8200,900 8248,852 9030,852 9078,900 R101.1@9300,900 R114.1@9750,900 R115.2@9850,900 ; R51.1@6600,2400 6648,2352 7652,2352 R74.1@7700,2400 R91.1@8200,2400 8250,2350 9250,2350 R106.1@9300,2400 R118.1@9800,2400
+15V: C6.1 C15.1 C30.1 C53.1 C58.1 C59.1 C62.1 C63.1 C66.1 C68.1 P1.48 R116.2 U1.4 U2.4 U3.4 U6.3 U7.3 U8.3 U9.3 U11.3 | length 23098
  Top Layer w12: v1(4616,1486) 4616,3146 4601,3161 4601,3225 4643,3267 4657,3267 4676,3248 4725,3248 4750.5,3273.5 4750.5,3313.5 4734,3330 4734,3563 4796,3625 4796,3696 P1.48@4850,3750 ; C62.1@8500,1300 8449,1351 8449,2051 8543.56,2145.56 8543.56,2756.44 C63.1@8500,2800 ; R116.2@9850,1600 9850,2550 C68.1@10100,2800
  Bottom Layer w12: C6.1@900,2050 U1.4@1000,2050 1150,1900 2950,1900 C30.1@3100,2050 U3.4@3200,2050 3384,1866 3384,1250 3434,1200 4566,1200 ; C15.1@2050,600 U2.4@2150,600 2196,646 2196,950 2163,983 1619,983 1601,1001 1601,1100 1685,1184 4550,1184 4566,1200 ; v1(4616,1486) 4616,1300 ; P1.48@4850,3750 4900,3700 4900,3596.17 4995.17,3501 5459.63,3501 C53.1@5560.63,3400 ; C58.1@6900,1300 U6.3@7000,1300 ; C59.1@6900,2800 U7.3@7000,2800 7050,2750 8450,2750 C63.1@8500,2800 U9.3@8600,2800 8651,2749 10049,2749 C68.1@10100,2800 U11.3@10200,2800 ; U8.3@8600,1300 C62.1@8500,1300 8451,1251 7049,1251 U6.3@7000,1300 ; C66.1@9700,1600 R116.2@9850,1600 ; 4566,1200 4616,1250 4616,1300 ; 4616,1300 4666,1250 5389.96,1250 5539.45,1100.51 5709.17,1100.51 5800.65,1191.99 6460.87,1191.99 6534.44,1265.56 6665.56,1265.56 6682.12,1249 6949,1249 U6.3@7000,1300
-1V: R123.1 R124.2 U6.4 U6.8 U7.4 U7.8 U8.4 U8.8 U9.4 U9.8 U11.4 | length 9354.2
  Top Layer w12: v1(7254,1050) 7254,946 U6.8@7300,900 ; U8.4@8600,1200 8649,1249 8649,2098 8667.53,2116.53 8667.53,2632.47 U9.4@8600,2700
  Bottom Layer w12: U6.4@7000,1200 7150,1050 v1(7254,1050) 7254,1125 7279,1150 8550,1150 U8.4@8600,1200 8832.47,967.53 8832.47,950 8850,932.47 8867.53,932.47 U8.8@8900,900 8935.06,900 8979.06,944 10206,944 R123.1@10250,900 R124.2@10350,900 ; U7.4@7000,2700 U7.8@7300,2400 7355,2455 8317,2455 8416,2554 8625,2554 ; U9.4@8600,2700 8646,2654 8646,2575 8625,2554 ; U9.8@8900,2400 8746,2554 8646,2554 ; U11.4@10200,2700 10150,2650 8742,2650 8646,2554 ; 8625,2554 8646,2554
-15V: C9.1 C22.1 C35.1 C55.2 C60.1 C61.1 C64.1 C65.1 C67.1 C69.1 P1.49 R125.2 U1.11 U2.5 U2.6 U2.9 U2.10 U2.11 U3.11 U6.12 U7.12 U8.12 U9.12 U11.8 U11.9 U11.10 U11.11 U11.12 | length 21976.2
  Top Layer w12: C9.1@1400,2050 1451.52,1998.48 1451.52,1629.92 1483.44,1598 1525,1598 1551,1572 1551,1030 2081,500 U2.5@2150,500 U2.6@2150,400 ; U2.9@2450,400 U2.10@2450,500 U2.11@2450,600 ; v1(4658,1650) 4644,1664 4644,3124 4787,3267 4787,3352 4756,3383 4756,3535 4821,3600 4900,3600 P1.49@4950,3650 ; C55.2@5939.37,3400 6001.37,3338 6059,3338 6096,3375 6096,3778 6125,3807 v1(6196,3807) ; R125.2@10350,1600 10500,1750 U11.8@10500,2400 U11.9@10500,2500 U11.10@10500,2600 U11.11@10500,2700 U11.12@10500,2800
  Bottom Layer w12: U1.11@1300,2050 C9.1@1400,2050 1454,2104 3432.47,2104 3454,2082.47 3467.53,2082.47 U3.11@3500,2050 ; U2.6@2150,400 U2.9@2450,400 ; U2.11@2450,600 C22.1@2550,600 ; C35.1@3600,2050 U3.11@3500,2050 ; v1(4658,1650) 4608,1600 3662,1600 3656,1594 3656,1525 3628,1497 3459,1497 3432,1524 3432,1982 U3.11@3500,2050 ; P1.49@4950,3650 5066,3534 5805.37,3534 C55.2@5939.37,3400 ; v1(6196,3807) 6207,3818 8189,3818 8196,3811 8196,3504 8850,2850 ; U6.12@7300,1300 C60.1@7400,1300 7451,1351 8849,1351 U8.12@8900,1300 C64.1@9000,1300 9049,1349 9949,1349 C67.1@10200,1600 R125.2@10350,1600 ; U7.12@7300,2800 C61.1@7400,2800 7450,2850 8850,2850 ; U11.10@10500,2600 C69.1@10600,2600 ; U11.12@10500,2800 10450,2850 9050,2850 C65.1@9000,2800 U9.12@8900,2800 8850,2850
AGND: C1.2 C2.2 C6.2 C7.2 C9.2 C13.2 C15.2 C17.2 C18.2 C20.2 C21.2 C22.2 C30.2 C31.2 C35.2 C39.2 C42.2 C43.2 C53.2 C55.1 C58.2 C59.2 C60.2 C61.2 C62.2 C63.2 C64.2 C65.2 C66.2 C67.2 C68.2 C69.2 P1.3 P1.6 P1.11 P1.14 P1.50 P2.9 P2.11 P2.13 P2.15 R7.2 R13.2 R29.2 R35.2 R50.2 R55.2 R64.1 R65.1 R66.1 R67.1 R68.2 R73.2 R84.2 R90.2 R96.1 R97.1 R98.1 R99.1 R100.2 R105.2 R114.2 R117.2 R123.2 R127.1 U1.5 U1.12 U2.3 U2.12 U3.5 U3.12 U10.1 U12.2
BRAKE_EN_RLY: D11.1 K3.6 U4.79 | length 696.4
  Top Layer w12: D11.1@5700,2444.09 5750,2394.09 U4.79@5750,1870.87
  Bottom Layer w12: D11.1@5700,2444.09 5747,2444.09 5752.91,2450 K3.6@5800,2450
DEC_EMERG_N: C48.1 P1.33 R46.1 U4.18 | length 2895.3
  Top Layer w12: R46.1@4800,3450 4846,3404 4846,2179 4742.83,2075.83 4742.83,1546.17 4789,1500 U4.18@4879.13,1500
  Bottom Layer w12: P1.33@4150,3650 4196,3604 4446,3604 C48.1@4650,3400 4750,3400 R46.1@4800,3450
DEC_EMERG_S: C49.1 P1.34 R47.1 U4.6 | length 2852
  Top Layer w12: R47.1@5100,3450 5032.47,3382.47 5032.47,2466.36 5010.47,2444.36 5010.47,2175.53 5200,1986 U4.6@5200,1870.87
  Bottom Layer w12: P1.34@4150,3750 4200,3700 4471,3700 4496,3675 4496,3604 4598,3502 4812,3502 4914,3400 C49.1@4950,3400 5050,3400 R47.1@5100,3450
DEC_STOP_N: C41.1 P1.31 R44.1 U4.67 | length 4067.1
  Top Layer w12: C41.1@4050,3400 P1.31@4050,3650 ; R44.1@4200,3450 4279.52,3370.48 4279.52,2229.52 4296,2213.04 v1(4296,1744) ; v1(5701,1437) 5766.13,1502.13 5908.87,1502.13 5961,1450 U4.67@6020.87,1450
  Bottom Layer w12: C41.1@4050,3400 4100,3450 R44.1@4200,3450 ; v1(4296,1744) 5269,1744 5576,1437 v1(5701,1437)
DEC_STOP_S: C45.1 P1.32 R45.1 U4.39 | length 4918.9
  Top Layer w12: P1.32@4050,3750 4100,3700 4100,3599 4150,3549 4201,3549 4256,3494 ; v1(4164,951) 4164,2031 4244,2111 4244,2804 4156,2892 4156,3475 4175,3494 4256,3494 ; C45.1@4350,3400 4256,3494 ; U4.39@5250,729.13 5250,861 v1(5307,918)
  Bottom Layer w12: v1(4164,951) 4550,951 4604,1005 4604,1096 4753.74,1096 4878.74,971 5254,971 v1(5307,918) ; C45.1@4350,3400 4400,3450 R45.1@4500,3450
DOME_ENABLE: D9.1 K1.6 U4.83 | length 1185
  Top Layer w12: v1(5475,1795) 5525,1795 5550,1820 U4.83@5550,1870.87
  Bottom Layer w12: D9.1@4700,2444.09 4747,2444.09 4752.91,2450 K1.6@4800,2450 5455,1795 v1(5475,1795)
GND: C23.2 C27.2 C32.2 C34.2 C38.2 C41.2 C45.2 C46.2 C47.2 C48.2 C49.2 C50.2 C51.2 C52.2 C54.2 C56.2 C57.2 JP1.1 JP1.3 JP1.5 JP1.7 JP1.9 JP1.11 JP1.13 P1.47 R48.2 U4.8 U4.16 U4.27 U4.42 U4.49 U4.60 U5.3 U5.4 | length 439.8
  Top Layer w12: v1(4805.83,1600) U4.16@4879.13,1600 ; U4.27@4879.13,1050 v1(4952.44,1050) ; U4.8@5100,1870.87 v1(5100,1944.17) ; v1(5400,655.83) U4.42@5400,729.13 ; U4.49@5750,729.13 v1(5750,802.44) ; U4.60@6020.87,1100 v1(6094.17,1100)
HA_EMERG_E: C38.1 P1.30 R38.1 U4.65 | length 3726
  Top Layer w12: R38.1@3900,3450 3900,3700 P1.30@3950,3750 ; v1(5805,1454) 5909,1350 U4.65@6020.87,1350
  Bottom Layer w12: C38.1@3750,3400 3850,3400 R38.1@3900,3450 3900,3216.14 4496,2620.14 4496,2536 4821.52,2210.48 4996.89,2210.48 5563.47,1643.91 5563.47,1617.53 5600,1581 5750,1581 5764,1567 5764,1495 v1(5805,1454)
HA_EMERG_W: C34.1 P1.29 R37.1 U4.26 | length 4777
  Top Layer w12: P1.29@3950,3650 3950,2921 3849,2820 3849,2000 3651.52,1802.52 3651.52,1628.46 3681.98,1598 3725,1598 3747,1576 3747,963 3800,910 4424,910 4582,1068 4582,1118 4796.74,1118 4814.74,1100 U4.26@4879.13,1100
  Bottom Layer w12: C34.1@3450,3400 3500,3450 R37.1@3600,3450 3643,3493 3829,3493 3950,3614 P1.29@3950,3650
HA_STOP_E: C32.1 P1.28 R33.1 U4.2 | length 3834.5
  Top Layer w12: P1.28@3850,3750 3909,3809 3975,3809 4001,3783 4001,3089 4002,3088 v1(4115,3088) ; v1(5350,2025) 5400,1975 U4.2@5400,1870.87
  Bottom Layer w12: C32.1@3150,3400 3200,3450 R33.1@3300,3450 3367,3517 3788,3517 3896,3625 3896,3704 P1.28@3850,3750 ; v1(4115,3088) 4233,3088 4846,2475 4846,2464 5285,2025 v1(5350,2025)
HA_STOP_W: C27.1 P1.27 R27.1 U4.37 | length 6134.3
  Top Layer w12: v1(3600,1948) 3805,2153 3805,2808 3850,2853 P1.27@3850,3650 ; U4.37@5150,729.13 5150,853 v1(5497.81,1200.81)
  Bottom Layer w12: C27.1@2850,3400 2900,3450 R27.1@3000,3450 3099,3549 3749,3549 P1.27@3850,3650 ; v1(3600,1948) 3555,1903 3482,1903 3454,1875 3454,1704 3457,1701 4558,1701 4570,1713 4985.63,1713 v1(5497.81,1200.81)
HORIZON_STOP: C23.1 P1.26 R24.1 U4.70 | length 5738.6
  Top Layer w12: v1(5701,1537) 5875.85,1537 5938.85,1600 U4.70@6020.87,1600
  Bottom Layer w12: P1.26@3750,3750 3700,3700 3700,3595 3687,3582 2991,3582 2859,3450 R24.1@2700,3450 2600,3450 C23.1@2550,3400 2684,3266 3606,3266 4150,2722 4287.35,2722 4474,2535.35 4474,2471 4761,2184 4979,2184 5511,1652 5511,1608 5582,1537 v1(5701,1537)
NetC1_1: C1.1 P1.4 R2.2 | length 3414.8
  Bottom Layer w12: C1.1@200,2400 R2.2@350,2400 350,2520 385,2555 926,2555 956,2525 956,2475 981,2450 1625,2450 1675,2500 1675,2873.99 2504,3702.99 2570.99,3702.99 2618,3750 P1.4@2650,3750
NetC2_1: C2.1 P1.5 R3.2 | length 2967.7
  Top Layer w12: v1(1920,3244) 2472,3796 2575,3796 2596,3775 2596,3728 2628,3696 2704,3696 P1.5@2750,3650
  Bottom Layer w12: C2.1@200,3000 R3.2@350,3000 594,3244 v1(1920,3244)
NetC3_1: C3.1 R1.2 | length 150
  Bottom Layer w12: R1.2@400,1650 C3.1@550,1650
NetC3_2: C3.2 C5.1 R4.2 R6.1 U1.6 | length 882.8
  Top Layer w12: C5.1@750,1800 850,1700 R4.2@850,1450
  Bottom Layer w12: C3.2@550,1850 600,1800 C5.1@750,1800 800,1850 R6.1@900,1850 U1.6@1000,1850
NetC4_1: C4.1 C8.2 R5.1 R9.2 R10.2 U1.1 | length 1220.4
  Top Layer w12: U1.1@1000,2350 R9.2@1000,2500 1075,2575 C8.2@1075,2600 1050,2625 R10.2@1050,2700
  Bottom Layer w12: C4.1@475,2050 525,2000 R5.1@600,2000 771,2000 975,2204 1025,2204 1046,2225 1046,2304 U1.1@1000,2350
NetC4_2: C4.2 R1.1 R5.2 | length 476.8
  Top Layer w12: R1.1@400,1950 400,2175 C4.2@475,2250
  Bottom Layer w12: C4.2@475,2250 525,2300 R5.2@600,2300
NetC5_2: C5.2 P2.10 R6.2 U1.7 | length 7539
  Top Layer w12: R6.2@900,1550 900,1650 U1.7@1000,1750 1224,1974 1224,3218 v1(1777,3771)
  Bottom Layer w12: C5.2@750,1600 800,1550 R6.2@900,1550 ; v1(1777,3771) 1825,3819 5021.6,3819 5236.6,3604 6275,3604 6296,3625 6296,3696 P2.10@6350,3750
NetC7_1: C7.1 D1.2 D2.1 R2.1 R7.1 U1.3 | length 1589.7
  Top Layer w12: D1.2@475,2900.91 618.09,3044 675,3044 700.37,3018.63 700.37,2544.47 D2.1@645,2489.09 645,2447 650,2442 R2.1@650,2400 ; R7.1@900,2500 949,2451 949,2201 U1.3@1000,2150
  Bottom Layer w12: D2.1@645,2489.09 717,2489.09 727.91,2500 C7.1@800,2500 R7.1@900,2500
NetC8_1: C8.1 D1.1 D2.2 R3.1 R9.1 U1.2 | length 1796.3
  Top Layer w12: D1.1@475,2489.09 645,2659.09 D2.2@645,2900.91 645,2947 650,2952 R3.1@650,3000 ; U1.2@1000,2250 1175,2425 C8.1@1175,2600
  Bottom Layer w12: D1.1@475,2489.09 714.09,2250 U1.2@1000,2250 ; C8.1@1175,2600 1275,2500 R9.1@1300,2500
NetC10_1: C10.1 D3.2 D4.1 R11.1 R15.1 U1.9 | length 1294.7
  Top Layer w12: R15.1@1750,2050 D3.2@1750,1955.91 1750,1694.09 D4.1@1900,1544.09
  Bottom Layer w12: U1.9@1300,1850 R11.1@1400,1850 C10.1@1500,1750 1694.09,1750 D4.1@1900,1544.09
NetC10_2: C10.2 C19.1 R8.1 R11.2 R18.1 U1.8 | length 1460.8
  Top Layer w12: R8.1@1300,1600 U1.8@1300,1750 ; C10.2@1500,1650 1679,1829 1679,2050 1723,2094 1844,2094 R18.1@2000,2250
  Bottom Layer w12: R8.1@1300,1600 1350,1550 R11.2@1400,1550 C10.2@1500,1650 ; R18.1@2000,2250 2050,2300 C19.1@2150,2300
NetC11_1: C11.1 C14.2 R12.1 R16.2 U1.13 | length 969.3
  Top Layer w12: C14.2@1750,2450 1706,2494 1706,2806 R16.2@1750,2850
  Bottom Layer w12: U1.13@1300,2250 R12.1@1400,2250 1450,2300 C11.1@1550,2300 1700,2450 C14.2@1750,2450
NetC11_2: C11.2 P2.8 R12.2 U1.14 | length 6428
  Top Layer w12: U1.14@1300,2350 1365.56,2415.56 1365.56,2515.56 R12.2@1400,2550
  Bottom Layer w12: R12.2@1400,2550 1450,2500 C11.2@1550,2500 1550,2790.05 2469.69,3709.74 2469.69,3765.69 2500,3796 4984.84,3796 5199,3581.84 6352.84,3581.84 6396,3625 6396,3775 6375,3796 6296,3796 P2.8@6250,3750
NetC12_1: C12.1 C16.1 R8.2 R10.1 R19.2 U2.2 | length 2826.3
  Top Layer w12: R8.2@1000,1600 1254,1854 1254,2604 R10.1@1350,2700
  Bottom Layer w12: R8.2@1000,1600 1000,1500 C12.1@1650,850 C16.1@1900,850 2000,750 R19.2@2050,750 2100,800 U2.2@2150,800
NetC12_2: C12.2 C16.2 P1.17 R19.1 R62.1 U2.1 | length 10531.2
  Top Layer w12: U2.1@2150,900 2050,1000 R19.1@2050,1050 2006,1094 2006,1600 2091,1685 2254,1685 2449,1880 2449,3632.5 2512.5,3696 2596.89,3696 2600,3692.89 2600,3629 2625,3604 v1(2804,3604) ; R62.1@6800,2225 6844,2181 6844,1694.28 6807,1657.28 v1(6807,1208)
  Bottom Layer w12: C12.2@1650,1050 C16.2@1900,1050 R19.1@2050,1050 2106,1106 4437.04,1106 4493.04,1162 5010.44,1162 5103.34,1069.1 5740.6,1069.1 5787.5,1116 6003.76,1116 6074.76,1045 6376.44,1045 6575,1243.56 6618.44,1243.56 6654,1208 v1(6807,1208) ; v1(2804,3604) 3304,3604 P1.17@3350,3650
NetC13_1: C13.1 D3.1 D4.2 R13.1 R14.1 U1.10 | length 1571.7
  Top Layer w12: U1.10@1300,1950 1351,1899 1351,1699 R13.1@1500,1550 ; D3.1@1750,1544.09 R14.1@1750,1450 1906,1450 1956,1500 1956,1899.91 D4.2@1900,1955.91
  Bottom Layer w12: R13.1@1500,1550 1550,1500 C13.1@1600,1500 1644.09,1544.09 D3.1@1750,1544.09
NetC14_1: C14.1 R17.2 | length 150
  Bottom Layer w12: C14.1@1750,2250 R17.2@1900,2250
NetC17_1: C17.1 P1.1 R14.2 | length 2679.8
  Top Layer w12: C17.1@2200,1250 2050,1400 R14.2@2050,1450 2248,1648 2266,1648 2484.44,1866.44 2484.44,3584.44 P1.1@2550,3650
NetC18_1: C18.1 P1.2 R15.2 | length 2182.9
  Top Layer w12: C18.1@2200,1850 2050,2000 R15.2@2050,2050 2050,3273.4 2496.38,3719.78 2519.78,3719.78 P1.2@2550,3750
NetC19_2: C19.2 R17.1 R18.2 | length 270.7
  Bottom Layer w12: R17.1@1900,2550 R18.2@2000,2550 2100,2550 C19.2@2150,2500
NetC20_1: C20.1 P1.12 R22.2 | length 1820.1
  Top Layer w12: R22.2@2550,2400 2686.28,2400 2755.37,2469.09 2755.37,2602.31 3044,2890.94 3044,3509 3004,3549 3004,3704 P1.12@3050,3750
  Bottom Layer w12: C20.1@2400,2400 R22.2@2550,2400
NetC21_1: C21.1 P1.13 R23.2 | length 1333.1
  Top Layer w12: v1(3115,3099) 3101,3113 3101,3448 3150,3497 P1.13@3150,3650
  Bottom Layer w12: C21.1@2400,3000 R23.2@2550,3000 2649,3099 v1(3115,3099)
NetC24_1: C24.1 C28.1 R21.2 R30.2 R32.1 U2.13 | length 4602.2
  Top Layer w12: C24.1@2700,850 2749,899 2749,1127 2701,1175 2701,1962 2724,1985 2724,2138 2906,2320 2906,2685 v1(2994,2773) ; C28.1@2950,850 2901,899 2901,1250 2983,1332 3150,1332 3200,1382 R30.2@3200,1600
  Bottom Layer w12: U2.13@2450,800 2500,750 R21.2@2550,750 2650,850 C24.1@2700,850 C28.1@2950,850 ; v1(2994,2773) 2915,2852 2915,2911 3000,2996 3254,2996 R32.1@3550,2700
NetC24_2: C24.2 C28.2 P1.18 R21.1 R79.1 U2.14 | length 9604.9
  Top Layer w12: U2.14@2450,900 2550,1000 R21.1@2550,1050 ; C28.2@2950,1050 3307.65,1407.65 3307.65,2401.81 3326,2420.16 3326,2682 3344,2700 3344,3509 3304,3549 3304,3704 P1.18@3350,3750 ; v1(7112,888) 7112,1722 7273,1883 7273,2063.91 7380.09,2171 7446,2171 R79.1@7500,2225
  Bottom Layer w12: R21.1@2550,1050 C24.2@2700,1050 C28.2@2950,1050 4381,1050 4445,986 4494,986 4577.11,1069.11 4577.11,1118 4802,1118 4911,1009 5776,1009 5824,1057 5954.5,1057 6045.5,966 6336,966 6621,681 6845.39,681 7052.39,888 v1(7112,888)
NetC25_1: C25.1 C33.2 R26.1 R31.2 R32.2 U3.1 | length 957.8
  Top Layer w12: U3.1@3200,2350 R31.2@3200,2500 3275,2575 C33.2@3275,2600 3250,2625 R32.2@3250,2700
  Bottom Layer w12: C25.1@2675,2250 2725,2300 R26.1@2800,2300 3150,2300 U3.1@3200,2350
NetC25_2: C25.2 R20.1 R26.2 | length 276.8
  Top Layer w12: R20.1@2600,1950 2675,2025 C25.2@2675,2050
  Bottom Layer w12: C25.2@2675,2050 2750,2050 R26.2@2800,2000
NetC26_1: C26.1 R20.2 | length 150
  Bottom Layer w12: R20.2@2600,1650 C26.1@2750,1650
NetC26_2: C26.2 C29.1 R25.2 R28.1 U3.6 | length 882.8
  Top Layer w12: C29.1@2950,1800 3050,1700 R25.2@3050,1450
  Bottom Layer w12: C26.2@2750,1850 2800,1800 C29.1@2950,1800 3000,1850 R28.1@3100,1850 U3.6@3200,1850
NetC29_2: C29.2 P2.14 R28.2 U3.7 | length 5956
  Top Layer w12: R28.2@3100,1550 3100,1650 U3.7@3200,1750 3246,1796 3246,2275 3217,2304 3154.47,2304 3154.47,2750 3242,2837.53 v1(3242,3325)
  Bottom Layer w12: C29.2@2950,1600 3000,1550 R28.2@3100,1550 ; v1(3242,3325) 3555,3325 3701,3471 3855,3471 3878,3494 4262,3494 4301,3455 4301,3375 4325,3351 5970.58,3351 5981.95,3362.37 5981.95,3450 6035.95,3504 6376.74,3504 6421.69,3548.95 6519.95,3548.95 6596,3625 6596,3704 P2.14@6550,3750
NetC31_1: C31.1 D5.2 D6.1 R22.1 R29.1 U3.3 | length 1737.7
  Top Layer w12: D5.2@2700,2905.91 2656,2861.91 2656,2543 2557,2444 2525,2444 2506.44,2425.44 2506.44,2374.56 2525,2356 2806,2356 R22.1@2850,2400 D6.1@2850,2494.09 ; R29.1@3100,2500 3100,2314.94 3149,2265.94 3149,2201 U3.3@3200,2150
  Bottom Layer w12: D6.1@2850,2494.09 2922,2494.09 2927.91,2500 C31.1@3000,2500 R29.1@3100,2500
NetC33_1: C33.1 D5.1 D6.2 R23.1 R31.1 U3.2 | length 2060.5
  Top Layer w12: D5.1@2700,2494.09 2700,2755.91 D6.2@2850,2905.91 R23.1@2850,3000
  Bottom Layer w12: D5.1@2700,2494.09 2755.91,2550 3131,2550 3156,2525 3156,2450 3210,2396 3271,2396 3322,2345 3377,2345 ; U3.2@3200,2250 3282,2250 3377,2345 ; R31.1@3500,2500 3400,2600 C33.1@3375,2600 3407,2568 3407,2375 3377,2345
